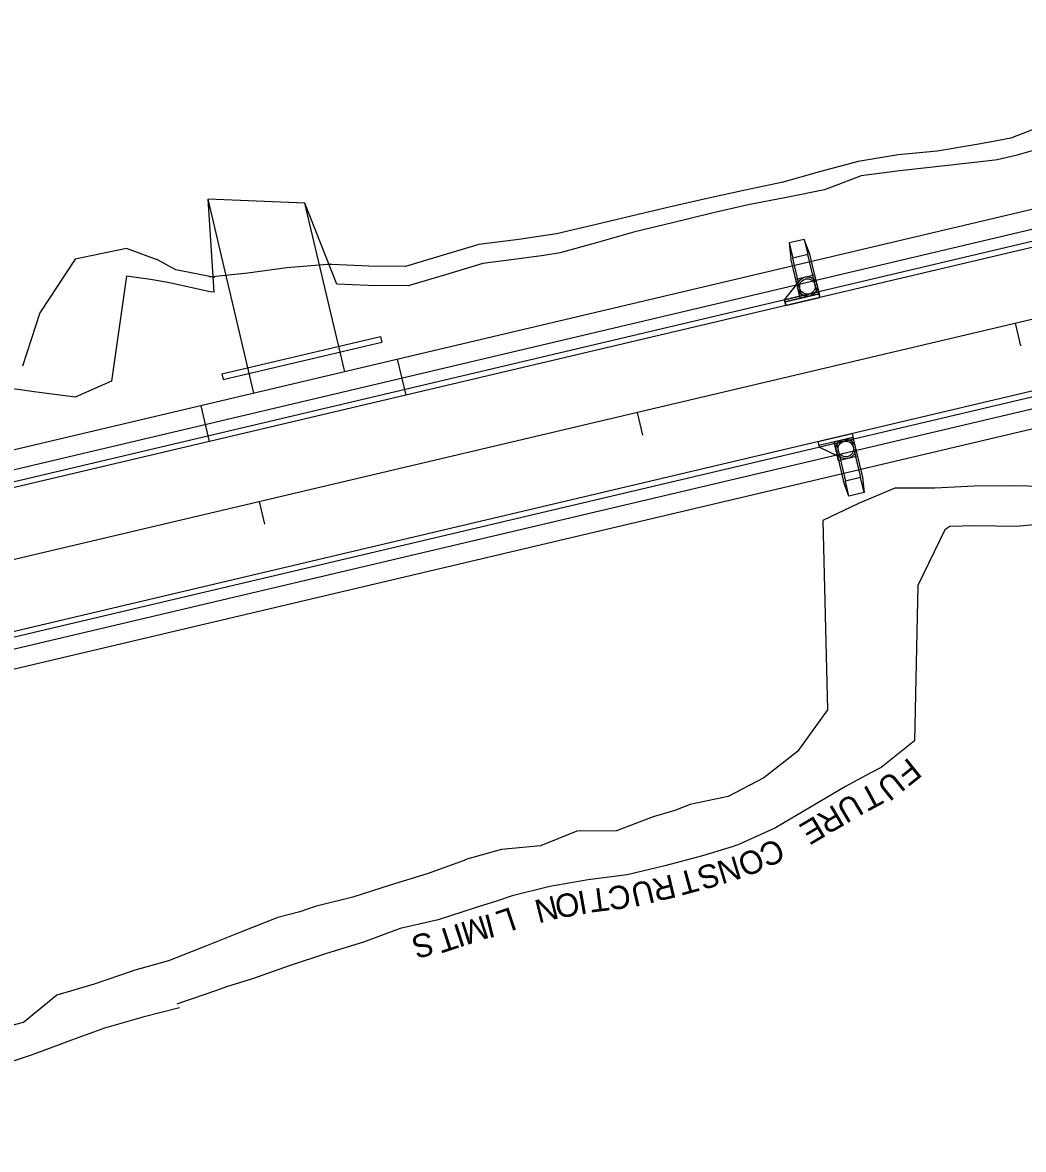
# Model space of a CAD drawing. Extents: x 979959 to 994833, y 1835619 to 1845316.
# Drawn here: x 981854.7 to 982112.4, y 1841650.8 to 1841941 of the extents above; entities that cross this region are included whole.
import ezdxf

# ---------------------------------------------------------------- set-up
doc = ezdxf.new("R2010")
doc.units = 0
for name, color, linetype in [('Future 5 Lane Construction Limits', 7, 'Continuous'), ('R_Drainage', 7, 'Continuous'), ('R_Horz Alg', 7, 'Continuous'), ('R_Horz Alg Stationing', 7, 'Continuous'), ('R_Proposed Const Limits', 7, 'Continuous'), ('R_Proposed Road', 7, 'Continuous')]:
    doc.layers.add(name, color=color, linetype=linetype)

msp = doc.modelspace()

# ---------------------------------------------------------------- linework, layer by layer
at = {"layer": 'Future 5 Lane Construction Limits'}
for points in [[(982128.58, 1841940.97), (982124.22, 1841919.37), (982117.57, 1841914.43), (982109.22, 1841911.21), (982104.23, 1841910.29), (982099.88, 1841909.49), (982090.18, 1841907.89), (982080.15, 1841906.87), (982069.88, 1841905.17), (982059.93, 1841902.56), (982050.25, 1841899.8)], [(982050.58, 1841899.88), (982040.79, 1841897.79), (982030.99, 1841895.65), (982021.18, 1841893.47), (982011.42, 1841891.13), (982001.71, 1841888.81), (981992.17, 1841886.59), (981988.2, 1841885.98), (981982.52, 1841885.15), (981972.16, 1841883.85), (981962.19, 1841880.79), (981953.33, 1841878.16), (981943.85, 1841878.28), (981934.38, 1841878.64), (981933.26, 1841878.69), (981922.73, 1841877.85), (981912.71, 1841876.47), (981902.77, 1841875.4)], [(981904.27, 1841875.33), (981894.2, 1841877.34), (981889.61, 1841879.75), (981881.45, 1841882.75), (981868.23, 1841880.03), (981859.15, 1841866.23), (981854.72, 1841852.47)], [(982130.68, 1841814.59), (982127.1, 1841813.49), (982121.73, 1841812.29), (982110.53, 1841811.26), (982099.87, 1841811.37), (982093.48, 1841811.24)], [(982093.48, 1841811.24), (982092.15, 1841810.33), (982085.25, 1841796.04), (982084.4, 1841756.08), (982075.76, 1841749.17), (982072.98, 1841747.73), (982066.63, 1841744.32), (982057.61, 1841738.99), (982048.6, 1841733.65), (982039.32, 1841729.41), (982037.7, 1841728.85), (982029.75, 1841726.44), (982020.09, 1841723.82), (982010.36, 1841721.51), (982000.39, 1841720.26), (981990.52, 1841718.53), (981980.82, 1841716.11), (981976.77, 1841714.74), (981972.02, 1841713.28), (981971.25, 1841713.08), (981961.71, 1841709.98), (981951.97, 1841707.72), (981942.52, 1841704.24), (981932.94, 1841701.27), (981923.41, 1841698.13), (981913.93, 1841694.75), (981907.5, 1841692.78), (981904.38, 1841691.7), (981894.87, 1841688.46), (981894.44, 1841688.28)], [(981895.14, 1841687.32), (981885.73, 1841684.87), (981885.46, 1841684.78), (981875.82, 1841682.08), (981866.37, 1841678.61), (981864.17, 1841677.8), (981856.91, 1841675.13), (981847.39, 1841671.95)]]:
    msp.add_lwpolyline(points, dxfattribs=at)
at = {"layer": 'R_Drainage'}
for p, q in [((982056, 1841885.15), (982052.1, 1841884.23)), ((982052.1, 1841884.23), (982052.54, 1841880.22)), ((982052.1, 1841884.23), (982053.02, 1841880.34)), ((982057.4, 1841881.37), (982056, 1841885.15)), ((982056, 1841885.15), (982056.92, 1841881.26)), ((982054.95, 1841870), (982052.54, 1841880.22)), ((982056.92, 1841881.26), (982053.02, 1841880.34)), ((982055.32, 1841870.61), (982053.02, 1841880.34)), ((982059.21, 1841871.52), (982056.92, 1841881.26)), ((982059.81, 1841871.15), (982057.4, 1841881.37)), ((982050.94, 1841869.57), (982054.84, 1841874.55)), ((982053.8, 1841874.87), (982058.67, 1841876.02)), ((982050.94, 1841869.57), (982054.1, 1841873.61)), ((982059.81, 1841871.15), (982051.05, 1841869.09)), ((982051.05, 1841869.09), (982059.81, 1841871.15)), ((982059.21, 1841871.52), (982055.32, 1841870.61)), ((981906.03, 1841850.53), (981946.91, 1841860.18)), ((981946.91, 1841860.18), (981947.25, 1841858.72)), ((981906.38, 1841849.07), (981947.25, 1841858.72)), ((981906.03, 1841850.53), (981906.38, 1841849.07)), ((982068.54, 1841834.17), (982059.78, 1841832.1)), ((982068.54, 1841834.17), (982059.78, 1841832.1)), ((982068.17, 1841833.57), (982064.28, 1841832.65)), ((982068.17, 1841833.57), (982070.47, 1841823.84)), ((982068.54, 1841834.17), (982070.95, 1841823.95)), ((982059.89, 1841831.62), (982065.61, 1841828.9)), ((982059.9, 1841831.62), (982064.53, 1841829.42)), ((982063.68, 1841833.02), (982066.09, 1841822.8)), ((982064.28, 1841832.65), (982066.58, 1841822.92)), ((982069.69, 1841829.3), (982064.82, 1841828.15)), ((982067.49, 1841819.02), (982066.09, 1841822.8)), ((982070.47, 1841823.84), (982066.58, 1841822.92)), ((982067.49, 1841819.02), (982066.58, 1841822.92)), ((982071.39, 1841819.94), (982070.47, 1841823.84)), ((982070.95, 1841823.95), (982071.39, 1841819.94)), ((982071.39, 1841819.94), (982067.49, 1841819.02))]:
    msp.add_line(p, q, dxfattribs=at)
for points in [[(982053.8, 1841874.87), (982058.67, 1841876.02), (982059.81, 1841871.15), (982054.95, 1841870)], [(982059.7, 1841871.64), (982050.94, 1841869.57), (982051.28, 1841868.11), (982060.04, 1841870.18)], [(982050.94, 1841869.57), (982059.7, 1841871.64), (982060.04, 1841870.18), (982051.28, 1841868.11)], [(982068.66, 1841833.68), (982059.9, 1841831.62), (982059.55, 1841833.08), (982068.31, 1841835.14)], [(982068.65, 1841833.68), (982059.89, 1841831.62), (982059.55, 1841833.08), (982068.31, 1841835.14)], [(982069.69, 1841829.3), (982064.82, 1841828.15), (982063.67, 1841833.02), (982068.54, 1841834.17)]]:
    msp.add_lwpolyline(points, close=True, dxfattribs=at)
for centre, radius in [((982056.81, 1841873.01), 2.5), ((982056.81, 1841873.01), 2.5), ((982056.81, 1841873.01), 2), ((982056.81, 1841873.01), 2), ((982066.68, 1841831.16), 2.5), ((982066.68, 1841831.16), 2.5), ((982066.68, 1841831.16), 2), ((982066.68, 1841831.16), 2)]:
    msp.add_circle(centre, radius, dxfattribs=at)
at = {"layer": 'R_Horz Alg'}
msp.add_line((982246.15, 1841895.6), (981814.34, 1841793.7), dxfattribs=at)
at = {"layer": 'R_Horz Alg Stationing'}
for points in [[(982111.79, 1841857.73), (982110.41, 1841863.57)], [(982014.46, 1841834.76), (982013.08, 1841840.6)], [(981917.13, 1841811.8), (981915.76, 1841817.63)]]:
    msp.add_lwpolyline(points, dxfattribs=at)
at = {"layer": 'R_Proposed Const Limits'}
for p, q in [((981904.08, 1841871.59), (981902.53, 1841895.47)), ((981935.68, 1841873.59), (981927.42, 1841894.48))]:
    msp.add_line(p, q, dxfattribs=at)
for points in [[(982124.77, 1841911.55), (982120.12, 1841909.5), (982110.51, 1841906.7), (982105.63, 1841905.6), (982105.1, 1841905.51), (982100.63, 1841905.02), (982090.62, 1841903.88), (982080.6, 1841902.83), (982070.63, 1841901.53), (982061.22, 1841897.87), (982051.39, 1841895.96), (982041.58, 1841894.01), (982031.82, 1841891.83), (982022.11, 1841889.43), (982012.4, 1841887.06), (982002.76, 1841884.36), (981993.12, 1841881.68), (981988.94, 1841881.03), (981983.19, 1841880.19), (981973.21, 1841878.94), (981963.63, 1841876), (981954.03, 1841873.16), (981943.72, 1841873.28), (981935.68, 1841873.59)], [(981904.08, 1841871.59), (981903.02, 1841871.6), (981892.16, 1841874.08), (981887.65, 1841874.85), (981881.5, 1841875.7), (981877.62, 1841848.6), (981868.3, 1841844.56)], [(981868.3, 1841844.56), (981857.71, 1841845.93), (981847.94, 1841847.23), (981847.09, 1841847.36), (981836.4, 1841849.12), (981825.31, 1841852.59), (981814.01, 1841856.95), (981812.26, 1841858.18), (981800.27, 1841871.63)], [(982148.26, 1841833.79), (982143.98, 1841830.15), (982139.45, 1841827.6), (982129.91, 1841824.49), (982125.13, 1841822.94), (982124.63, 1841822.78), (982120.35, 1841821.45), (982110.02, 1841821.7), (982099.76, 1841821.62), (982089.6, 1841821.13), (982079.35, 1841821.05)], [(982079.35, 1841821.05), (982069.99, 1841817.14), (982060.75, 1841812.76), (982061.99, 1841763.99), (982054.23, 1841753.32), (982045.56, 1841746.52), (982036.42, 1841741.71), (982026.63, 1841739.65), (982022.66, 1841738.15), (982017.11, 1841736.45), (982007.69, 1841732.86), (981997.44, 1841732.75), (981988.04, 1841729.01), (981978, 1841728.03), (981969.11, 1841725.61), (981968.39, 1841725.23), (981958.93, 1841721.77), (981949.33, 1841718.92), (981939.79, 1841715.78), (981930.09, 1841713.38), (981926.08, 1841712.02), (981920.47, 1841710.6), (981911.07, 1841706.89), (981901.68, 1841703.13), (981892.29, 1841699.4), (981883.41, 1841696.92), (981882.66, 1841696.67), (981873.14, 1841693.44), (981863.55, 1841690.55), (981859.25, 1841687.02)], [(981859.25, 1841687.02), (981854.94, 1841683.49), (981853.57, 1841683.16), (981845.25, 1841681.04), (981836.69, 1841679.14), (981829.27, 1841676.46), (981821.78, 1841674.11), (981814.42, 1841671.33), (981807.7, 1841668.68), (981807.68, 1841668.68), (981807.1, 1841668.53), (981800.05, 1841664.98), (981794.92, 1841662.69), (981792.91, 1841661.77), (981785.8, 1841658.55), (981778.75, 1841655.24), (981772.18, 1841650.84), (981761.26, 1841656.15), (981750.55, 1841660.24), (981740.6, 1841662.11), (981729.7, 1841665.34), (981715.82, 1841673.41), (981710.7, 1841674.66)]]:
    msp.add_lwpolyline(points, dxfattribs=at)
at = {"layer": 'R_Proposed Road'}
for p, q in [((982239.83, 1841922.37), (981808.02, 1841820.47)), ((982240.98, 1841917.5), (981809.17, 1841815.6)), ((982241.67, 1841914.58), (981809.86, 1841812.68)), ((982242.02, 1841913.12), (981810.2, 1841811.22)), ((981927.42, 1841894.48), (981902.53, 1841895.47)), ((982250.29, 1841878.09), (981818.47, 1841776.18)), ((982250.63, 1841876.63), (981818.82, 1841774.72)), ((982251.32, 1841873.71), (981819.5, 1841771.8)), ((982252.47, 1841868.84), (981820.65, 1841766.94))]:
    msp.add_line(p, q, dxfattribs=at)
for points in [[(981914.31, 1841845.55), (981902.53, 1841895.47)], [(981937.67, 1841851.06), (981927.42, 1841894.48)], [(981953.47, 1841845.03), (981951.29, 1841854.28)], [(981902.86, 1841833.09), (981900.68, 1841842.33)]]:
    msp.add_lwpolyline(points, dxfattribs=at)

# ---------------------------------------------------------------- texts
at = {"layer": 'Future 5 Lane Construction Limits'}
for s, rotation, p in [('F', 218.6622, (982082.95, 1841751.93)), ('U', 218.6622, (982078.74, 1841748.57)), ('T', 208.2276, (982073.92, 1841745.45)), ('U', 210.5876, (982068.73, 1841742.74)), ('R', 210.5876, (982063.77, 1841739.8)), ('E', 210.6355, (982058.89, 1841736.92)), ('C', 204.5974, (982049.08, 1841731.15)), ('N', 196.8578, (982038.54, 1841726.49)), ('O', 204.5974, (982043.92, 1841728.79)), ('S', 196.8578, (982033.11, 1841724.85)), ('R', 193.3498, (982022.02, 1841721.72)), ('T', 195.1753, (982027.66, 1841723.29)), ('I', 189.9513, (981999.46, 1841717.58)), ('T', 187.1681, (982005.26, 1841718.4)), ('C', 187.1681, (982010.89, 1841719.1)), ('U', 193.3498, (982016.5, 1841720.41)), ('N', 193.9973, (981991.73, 1841716.26)), ('O', 189.9513, (981997.51, 1841717.24)), ('L', 198.715, (981980.44, 1841713.34)), ('I', 198.0196, (981967.29, 1841709.17)), ('M', 198.0196, (981973.4, 1841711.16)), ('I', 194.2824, (981975.35, 1841711.55)), ('S', 193.062, (981959.77, 1841706.97)), ('T', 198.0196, (981965.4, 1841708.55))]:
    msp.add_text(s, height=6, rotation=rotation, dxfattribs=at).set_placement(p)

doc.saveas('drawing.dxf')
